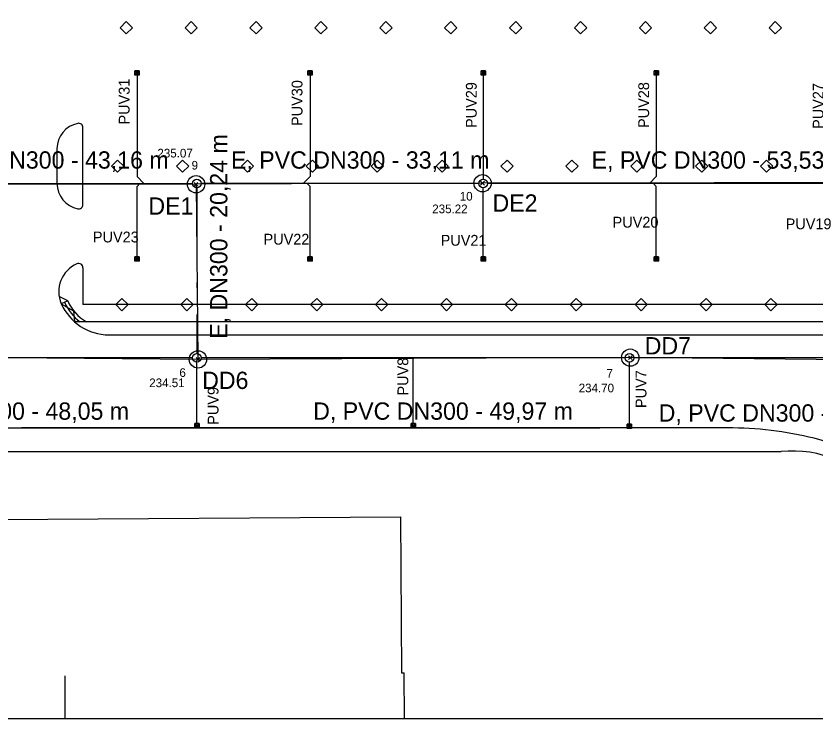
# Model space of a CAD drawing. Extents: x -264234 to -263604, y -1242346 to -1242049.
# Drawn here: x -263924.8 to -263832.4, y -1242345.9 to -1242264.6 of the extents above; entities that cross this region are included whole.
import ezdxf

# ---------------------------------------------------------------- set-up
doc = ezdxf.new("R2010")
doc.units = 0
for name, color, linetype in [('KFA_BODY_CISLO', 7, 'Continuous'), ('KFA_BODY_SYMBOL', 7, 'Continuous'), ('KFA_BODY_VYSKA', 7, 'Continuous'), ('KFA_DAZDOVA_KANALIZACIA_vetva_D', 7, 'Continuous'), ('KFA_DAZDOVA_KANALIZACIA_vetva_D_popis', 7, 'Continuous'), ('KFA_DAZDOVA_KANALIZACIA_vetva_E', 7, 'Continuous'), ('KFA_DAZDOVA_KANALIZACIA_vetva_E_popis', 7, 'Continuous'), ('KFA_SITUACIA_DSP', 7, 'Continuous'), ('KFA_SO_40-2-II_DK_PRIPOJKY_UV_PROJEKT', 7, 'Continuous'), ('KFA_SO_40-2-II_DK_PRIPOJKY_UV_PROJEKT_popis', 7, 'Continuous'), ('KFA_SO_40-2-II_DK_UV_PROJEKT', 7, 'Continuous'), ('RAM_NA_TLAC_1-500', 7, 'Continuous')]:
    doc.layers.add(name, color=color, linetype=linetype)

msp = doc.modelspace()

# ---------------------------------------------------------------- linework, layer by layer
at = {"layer": 'KFA_BODY_SYMBOL'}
for p, q in [((-263871.119, -1242284.177), (-263870.677, -1242283.735)), ((-263870.677, -1242284.177), (-263871.119, -1242283.735)), ((-263904.23, -1242284.301), (-263903.788, -1242283.859)), ((-263903.788, -1242284.301), (-263904.23, -1242283.859)), ((-263904.008, -1242304.539), (-263903.566, -1242304.097)), ((-263903.566, -1242304.539), (-263904.008, -1242304.097)), ((-263854.043, -1242304.34), (-263853.601, -1242303.898)), ((-263853.601, -1242304.34), (-263854.043, -1242303.898))]:
    msp.add_line(p, q, dxfattribs=at)
at = {"layer": 'KFA_DAZDOVA_KANALIZACIA_vetva_D'}
msp.add_lwpolyline([(-263821.591, -1242304.454), (-263853.822, -1242304.119), (-263903.787, -1242304.318), (-263951.83, -1242303.896), (-264004.174, -1242304.048), (-264044.816, -1242304.218), (-264095.209, -1242304.148), (-264105.621, -1242304.173)], dxfattribs=at)
for centre in [(-263853.822, -1242304.119), (-263903.787, -1242304.318)]:
    msp.add_circle(centre, 1, dxfattribs=at)
at = {"layer": 'KFA_DAZDOVA_KANALIZACIA_vetva_E'}
for p, q in [((-263947.171, -1242284.013), (-263904.009, -1242284.08)), ((-263904.009, -1242284.08), (-263903.787, -1242304.318))]:
    msp.add_line(p, q, dxfattribs=at)
msp.add_lwpolyline([(-263817.366, -1242283.882), (-263870.898, -1242283.956), (-263904.009, -1242284.08)], dxfattribs=at)
for centre in [(-263904.009, -1242284.08), (-263870.898, -1242283.956)]:
    msp.add_circle(centre, 1, dxfattribs=at)
at = {"layer": 'KFA_SITUACIA_DSP'}
for p, q in [((-263911.074, -1242270.983), (-263910.574, -1242270.983)), ((-263911.074, -1242271.273), (-263911.074, -1242270.983)), ((-263911.074, -1242270.983), (-263910.574, -1242271.273)), ((-263911.074, -1242270.983), (-263910.574, -1242271.273)), ((-263910.574, -1242270.983), (-263911.074, -1242270.983)), ((-263910.574, -1242271.273), (-263911.074, -1242271.273)), ((-263910.824, -1242271.473), (-263910.824, -1242283.187)), ((-263910.574, -1242270.983), (-263910.574, -1242271.273)), ((-263910.574, -1242271.273), (-263910.574, -1242270.983)), ((-263891.074, -1242270.983), (-263890.574, -1242270.983)), ((-263891.074, -1242271.273), (-263891.074, -1242270.983)), ((-263891.074, -1242270.983), (-263890.574, -1242271.273)), ((-263891.074, -1242270.983), (-263890.574, -1242271.273)), ((-263890.574, -1242270.983), (-263891.074, -1242270.983)), ((-263890.574, -1242271.273), (-263891.074, -1242271.273)), ((-263890.824, -1242271.473), (-263890.824, -1242283.187)), ((-263890.574, -1242270.983), (-263890.574, -1242271.273)), ((-263890.574, -1242271.273), (-263890.574, -1242270.983)), ((-263871.074, -1242270.983), (-263870.574, -1242270.983)), ((-263871.074, -1242271.273), (-263871.074, -1242270.983)), ((-263871.074, -1242270.983), (-263870.574, -1242271.273)), ((-263871.074, -1242270.983), (-263870.574, -1242271.273)), ((-263870.574, -1242270.983), (-263871.074, -1242270.983)), ((-263870.574, -1242271.273), (-263871.074, -1242271.273)), ((-263870.824, -1242271.473), (-263870.824, -1242283.482)), ((-263870.574, -1242270.983), (-263870.574, -1242271.273)), ((-263870.574, -1242271.273), (-263870.574, -1242270.983)), ((-263851.074, -1242270.983), (-263850.574, -1242270.983)), ((-263851.074, -1242271.273), (-263851.074, -1242270.983)), ((-263851.074, -1242270.983), (-263850.574, -1242271.273)), ((-263851.074, -1242270.983), (-263850.574, -1242271.273)), ((-263850.574, -1242270.983), (-263851.074, -1242270.983)), ((-263850.574, -1242271.273), (-263851.074, -1242271.273)), ((-263850.824, -1242271.473), (-263850.824, -1242283.187)), ((-263850.574, -1242270.983), (-263850.574, -1242271.273)), ((-263850.574, -1242271.273), (-263850.574, -1242270.983)), ((-263917.08, -1242286.432), (-263917.08, -1242277.533)), ((-263920.08, -1242279.982), (-263920.08, -1242283.982)), ((-263910.824, -1242283.187), (-263910.029, -1242283.982)), ((-263890.824, -1242283.187), (-263891.619, -1242283.982)), ((-263850.824, -1242283.187), (-263851.619, -1242283.982)), ((-263946.608, -1242283.982), (-263908.955, -1242283.982)), ((-263946.608, -1242283.982), (-263904.413, -1242283.982)), ((-263910.824, -1242284.343), (-263910.499, -1242283.982)), ((-263910.824, -1242292.492), (-263910.824, -1242284.343)), ((-263903.913, -1242284.482), (-263903.913, -1242292.347)), ((-263871.324, -1242283.982), (-263903.413, -1242283.982)), ((-263890.824, -1242284.343), (-263891.149, -1242283.982)), ((-263890.824, -1242292.492), (-263890.824, -1242284.343)), ((-263870.824, -1242292.492), (-263870.824, -1242284.482)), ((-263817.941, -1242283.982), (-263870.324, -1242283.982)), ((-263817.941, -1242283.982), (-263870.324, -1242283.982)), ((-263850.824, -1242284.343), (-263851.149, -1242283.982)), ((-263850.824, -1242292.492), (-263850.824, -1242284.343)), ((-263911.074, -1242292.692), (-263910.574, -1242292.692)), ((-263911.074, -1242292.982), (-263911.074, -1242292.692)), ((-263911.074, -1242292.692), (-263910.574, -1242292.982)), ((-263911.074, -1242292.692), (-263910.574, -1242292.982)), ((-263910.574, -1242292.692), (-263911.074, -1242292.692)), ((-263910.574, -1242292.982), (-263911.074, -1242292.982)), ((-263910.574, -1242292.692), (-263910.574, -1242292.982)), ((-263910.574, -1242292.982), (-263910.574, -1242292.692)), ((-263891.074, -1242292.693), (-263890.574, -1242292.693)), ((-263891.074, -1242292.983), (-263891.074, -1242292.693)), ((-263891.074, -1242292.693), (-263890.574, -1242292.983)), ((-263891.074, -1242292.693), (-263890.574, -1242292.983)), ((-263890.574, -1242292.693), (-263891.074, -1242292.693)), ((-263890.574, -1242292.983), (-263891.074, -1242292.983)), ((-263890.574, -1242292.693), (-263890.574, -1242292.983)), ((-263890.574, -1242292.983), (-263890.574, -1242292.693)), ((-263871.074, -1242292.693), (-263870.574, -1242292.693)), ((-263871.074, -1242292.983), (-263871.074, -1242292.693)), ((-263871.074, -1242292.693), (-263870.574, -1242292.983)), ((-263871.074, -1242292.693), (-263870.574, -1242292.983)), ((-263870.574, -1242292.693), (-263871.074, -1242292.693)), ((-263870.574, -1242292.983), (-263871.074, -1242292.983)), ((-263870.574, -1242292.693), (-263870.574, -1242292.983)), ((-263870.574, -1242292.983), (-263870.574, -1242292.693)), ((-263851.074, -1242292.693), (-263850.574, -1242292.693)), ((-263851.074, -1242292.983), (-263851.074, -1242292.693)), ((-263851.074, -1242292.693), (-263850.574, -1242292.983)), ((-263851.074, -1242292.693), (-263850.574, -1242292.983)), ((-263850.574, -1242292.693), (-263851.074, -1242292.693)), ((-263850.574, -1242292.983), (-263851.074, -1242292.983)), ((-263850.574, -1242292.693), (-263850.574, -1242292.983)), ((-263850.574, -1242292.983), (-263850.574, -1242292.693)), ((-263917.08, -1242293.737), (-263917.08, -1242297.982)), ((-263903.913, -1242295.447), (-263903.913, -1242296.047)), ((-263918.846, -1242297.562), (-263919.828, -1242297.035)), ((-263918.846, -1242297.562), (-263919.579, -1242297.882)), ((-263815.601, -1242297.982), (-263917.08, -1242297.982)), ((-263903.913, -1242299.147), (-263903.913, -1242303.647)), ((-263816.308, -1242299.982), (-263918.049, -1242299.982)), ((-263914.08, -1242301.482), (-263815.822, -1242301.482)), ((-263904.413, -1242304.147), (-263953.413, -1242304.147)), ((-263854.415, -1242304.147), (-263903.413, -1242304.147)), ((-263878.913, -1242311.742), (-263878.913, -1242304.147)), ((-263809.091, -1242304.153), (-263853.415, -1242304.148)), ((-263903.913, -1242311.742), (-263903.913, -1242304.647)), ((-263853.915, -1242311.749), (-263853.915, -1242304.647)), ((-263980.94, -1242312.232), (-263857.327, -1242312.232)), ((-263842.601, -1242312.24), (-263924.192, -1242312.232)), ((-263904.163, -1242311.942), (-263903.663, -1242311.942)), ((-263904.163, -1242312.232), (-263904.163, -1242311.942)), ((-263904.163, -1242311.942), (-263903.663, -1242312.232)), ((-263904.163, -1242311.942), (-263903.663, -1242312.232)), ((-263903.663, -1242311.942), (-263904.163, -1242311.942)), ((-263903.663, -1242312.232), (-263904.163, -1242312.232)), ((-263903.663, -1242311.942), (-263903.663, -1242312.232)), ((-263903.663, -1242312.232), (-263903.663, -1242311.942)), ((-263879.163, -1242311.942), (-263878.663, -1242311.942)), ((-263879.163, -1242312.232), (-263879.163, -1242311.942)), ((-263879.163, -1242311.942), (-263878.663, -1242312.232)), ((-263879.163, -1242311.942), (-263878.663, -1242312.232)), ((-263878.663, -1242311.942), (-263879.163, -1242311.942)), ((-263878.663, -1242312.232), (-263879.163, -1242312.232)), ((-263878.663, -1242311.942), (-263878.663, -1242312.232)), ((-263878.663, -1242312.232), (-263878.663, -1242311.942)), ((-263854.165, -1242311.949), (-263853.665, -1242311.949)), ((-263854.165, -1242312.239), (-263854.165, -1242311.949)), ((-263854.165, -1242311.949), (-263853.665, -1242312.239)), ((-263854.165, -1242311.949), (-263853.665, -1242312.239)), ((-263853.665, -1242311.949), (-263854.165, -1242311.949)), ((-263853.665, -1242312.239), (-263854.165, -1242312.239)), ((-263853.665, -1242311.949), (-263853.665, -1242312.239)), ((-263853.665, -1242312.239), (-263853.665, -1242311.949)), ((-264038.443, -1242314.982), (-263836.403, -1242314.982)), ((-263976.89, -1242323.14), (-263880.39, -1242322.51)), ((-263880.39, -1242322.51), (-263880.27, -1242340.53)), ((-263880.27, -1242340.53), (-263879.95, -1242340.53)), ((-263879.909, -1242345.883), (-263879.95, -1242340.53))]:
    msp.add_line(p, q, dxfattribs=at)
for points in [[(-263912.068, -1242265.279), (-263911.361, -1242265.986), (-263912.068, -1242266.693), (-263912.775, -1242265.986)], [(-263904.568, -1242265.279), (-263903.861, -1242265.986), (-263904.568, -1242266.693), (-263905.275, -1242265.986)], [(-263897.068, -1242265.279), (-263896.361, -1242265.986), (-263897.068, -1242266.693), (-263897.775, -1242265.986)], [(-263897.068, -1242265.279), (-263896.361, -1242265.986), (-263897.068, -1242266.693), (-263897.775, -1242265.986)], [(-263889.568, -1242265.279), (-263888.861, -1242265.986), (-263889.568, -1242266.693), (-263890.275, -1242265.986)], [(-263882.068, -1242265.279), (-263881.361, -1242265.986), (-263882.068, -1242266.693), (-263882.775, -1242265.986)], [(-263874.568, -1242265.279), (-263873.861, -1242265.986), (-263874.568, -1242266.693), (-263875.275, -1242265.986)], [(-263867.068, -1242265.279), (-263866.361, -1242265.986), (-263867.068, -1242266.693), (-263867.775, -1242265.986)], [(-263859.568, -1242265.279), (-263858.861, -1242265.986), (-263859.568, -1242266.693), (-263860.275, -1242265.986)], [(-263852.068, -1242265.279), (-263851.361, -1242265.986), (-263852.068, -1242266.693), (-263852.775, -1242265.986)], [(-263844.568, -1242265.279), (-263843.861, -1242265.986), (-263844.568, -1242266.693), (-263845.275, -1242265.986)], [(-263837.068, -1242265.279), (-263836.361, -1242265.986), (-263837.068, -1242266.693), (-263837.775, -1242265.986)], [(-263913.068, -1242281.275), (-263912.361, -1242281.982), (-263913.068, -1242282.689), (-263913.775, -1242281.982)], [(-263905.568, -1242281.275), (-263904.861, -1242281.982), (-263905.568, -1242282.689), (-263906.275, -1242281.982)], [(-263898.068, -1242281.275), (-263897.361, -1242281.982), (-263898.068, -1242282.689), (-263898.775, -1242281.982)], [(-263890.568, -1242281.275), (-263889.861, -1242281.982), (-263890.568, -1242282.689), (-263891.275, -1242281.982)], [(-263890.568, -1242281.275), (-263889.861, -1242281.982), (-263890.568, -1242282.689), (-263891.275, -1242281.982)], [(-263883.068, -1242281.275), (-263882.361, -1242281.982), (-263883.068, -1242282.689), (-263883.775, -1242281.982)], [(-263875.568, -1242281.275), (-263874.861, -1242281.982), (-263875.568, -1242282.689), (-263876.275, -1242281.982)], [(-263868.068, -1242281.275), (-263867.361, -1242281.982), (-263868.068, -1242282.689), (-263868.775, -1242281.982)], [(-263860.568, -1242281.275), (-263859.861, -1242281.982), (-263860.568, -1242282.689), (-263861.275, -1242281.982)], [(-263853.068, -1242281.275), (-263852.361, -1242281.982), (-263853.068, -1242282.689), (-263853.775, -1242281.982)], [(-263845.568, -1242281.275), (-263844.861, -1242281.982), (-263845.568, -1242282.689), (-263846.275, -1242281.982)], [(-263838.068, -1242281.275), (-263837.361, -1242281.982), (-263838.068, -1242282.689), (-263838.775, -1242281.982)], [(-263912.568, -1242297.275), (-263911.861, -1242297.982), (-263912.568, -1242298.689), (-263913.275, -1242297.982)], [(-263905.068, -1242297.275), (-263904.361, -1242297.982), (-263905.068, -1242298.689), (-263905.775, -1242297.982)], [(-263897.568, -1242297.275), (-263896.861, -1242297.982), (-263897.568, -1242298.689), (-263898.275, -1242297.982)], [(-263890.068, -1242297.275), (-263889.361, -1242297.982), (-263890.068, -1242298.689), (-263890.775, -1242297.982)], [(-263890.068, -1242297.275), (-263889.361, -1242297.982), (-263890.068, -1242298.689), (-263890.775, -1242297.982)], [(-263882.568, -1242297.275), (-263881.861, -1242297.982), (-263882.568, -1242298.689), (-263883.275, -1242297.982)], [(-263875.068, -1242297.275), (-263874.361, -1242297.982), (-263875.068, -1242298.689), (-263875.775, -1242297.982)], [(-263867.568, -1242297.275), (-263866.861, -1242297.982), (-263867.568, -1242298.689), (-263868.275, -1242297.982)], [(-263860.068, -1242297.275), (-263859.361, -1242297.982), (-263860.068, -1242298.689), (-263860.775, -1242297.982)], [(-263852.568, -1242297.275), (-263851.861, -1242297.982), (-263852.568, -1242298.689), (-263853.275, -1242297.982)], [(-263845.068, -1242297.275), (-263844.361, -1242297.982), (-263845.068, -1242298.689), (-263845.775, -1242297.982)], [(-263837.568, -1242297.275), (-263836.861, -1242297.982), (-263837.568, -1242298.689), (-263838.275, -1242297.982)]]:
    msp.add_lwpolyline(points, close=True, dxfattribs=at)
msp.add_lwpolyline([(-263919.579, -1242297.882), (-263918.155, -1242298.713), (-263918.049, -1242299.982)], dxfattribs=at)
for centre, radius in [((-263910.824, -1242271.373), 0.1), ((-263890.824, -1242271.373), 0.1), ((-263870.824, -1242271.373), 0.1), ((-263850.824, -1242271.373), 0.1), ((-263903.913, -1242283.982), 0.5), ((-263870.824, -1242283.982), 0.5), ((-263910.824, -1242292.592), 0.1), ((-263890.824, -1242292.592), 0.1), ((-263870.824, -1242292.592), 0.1), ((-263850.824, -1242292.592), 0.1), ((-263903.913, -1242304.147), 0.5), ((-263853.915, -1242304.147), 0.5), ((-263903.913, -1242311.842), 0.1), ((-263878.913, -1242311.842), 0.1), ((-263853.915, -1242311.849), 0.1)]:
    msp.add_circle(centre, radius, dxfattribs=at)
for centre, radius, start, end in [((-263917.08, -1242279.982), 3, 101.53696, 180), ((-263917.58, -1242277.533), 0.5, 0, 101.53696), ((-263917.08, -1242283.982), 3, 180, 258.46304), ((-263917.58, -1242286.432), 0.5, 258.46304, 0), ((-263916.372, -1242296.482), 3.5, 113.75985, 203.57818), ((-263917.58, -1242293.737), 0.5, 0, 113.75985), ((-263914.08, -1242295.482), 5.2, 203.57818, 239.92665), ((-263914.08, -1242295.482), 6, 203.57818, 270), ((-263914.08, -1242295.482), 5.6, 203.57818, 233.47251), ((-263842.427, -1242353.351), 41.111, 76.13622, 90.24149), ((-263836.184, -1242329.025), 16, 326.2529, 76.96946), ((-263835.045, -1242327.715), 12.805, 36.92053, 96.08735)]:
    msp.add_arc(centre, radius, start, end, dxfattribs=at)
at = {"layer": 'KFA_SO_40-2-II_DK_PRIPOJKY_UV_PROJEKT'}
for points in [[(-263910.824, -1242271.473), (-263910.824, -1242283.187), (-263910.029, -1242283.982)], [(-263890.824, -1242271.473), (-263890.824, -1242283.187), (-263891.619, -1242283.982)], [(-263870.824, -1242271.473), (-263870.824, -1242283.482)], [(-263850.824, -1242271.473), (-263850.824, -1242283.187), (-263851.619, -1242283.982)], [(-263910.824, -1242292.492), (-263910.824, -1242284.343), (-263910.499, -1242283.982)], [(-263890.824, -1242292.492), (-263890.824, -1242284.343), (-263891.149, -1242283.982)], [(-263870.824, -1242292.492), (-263870.824, -1242284.482)], [(-263850.824, -1242292.492), (-263850.824, -1242284.343), (-263851.149, -1242283.982)], [(-263878.913, -1242311.742), (-263878.913, -1242304.147)], [(-263903.913, -1242311.742), (-263903.913, -1242304.647)], [(-263853.915, -1242311.749), (-263853.915, -1242304.647)]]:
    msp.add_lwpolyline(points, dxfattribs=at)
at = {"layer": 'KFA_SO_40-2-II_DK_UV_PROJEKT'}
for points in [[(-263911.074, -1242271.483), (-263911.074, -1242270.983), (-263910.574, -1242270.983), (-263910.574, -1242271.483), (-263911.074, -1242271.483), (-263910.574, -1242270.983), (-263911.074, -1242270.983), (-263910.574, -1242271.483)], [(-263891.074, -1242271.483), (-263891.074, -1242270.983), (-263890.574, -1242270.983), (-263890.574, -1242271.483), (-263891.074, -1242271.483), (-263890.574, -1242270.983), (-263891.074, -1242270.983), (-263890.574, -1242271.483)], [(-263871.074, -1242271.483), (-263871.074, -1242270.983), (-263870.574, -1242270.983), (-263870.574, -1242271.483), (-263871.074, -1242271.483), (-263870.574, -1242270.983), (-263871.074, -1242270.983), (-263870.574, -1242271.483)], [(-263851.074, -1242271.483), (-263851.074, -1242270.983), (-263850.574, -1242270.983), (-263850.574, -1242271.483), (-263851.074, -1242271.483), (-263850.574, -1242270.983), (-263851.074, -1242270.983), (-263850.574, -1242271.483)], [(-263911.074, -1242292.982), (-263911.074, -1242292.482), (-263910.574, -1242292.482), (-263910.574, -1242292.982), (-263911.074, -1242292.982), (-263910.574, -1242292.482), (-263911.074, -1242292.482), (-263910.574, -1242292.982)], [(-263891.074, -1242292.983), (-263891.074, -1242292.483), (-263890.574, -1242292.483), (-263890.574, -1242292.983), (-263891.074, -1242292.983), (-263890.574, -1242292.483), (-263891.074, -1242292.483), (-263890.574, -1242292.983)], [(-263871.074, -1242292.983), (-263871.074, -1242292.483), (-263870.574, -1242292.483), (-263870.574, -1242292.983), (-263871.074, -1242292.983), (-263870.574, -1242292.483), (-263871.074, -1242292.483), (-263870.574, -1242292.983)], [(-263851.074, -1242292.983), (-263851.074, -1242292.483), (-263850.574, -1242292.483), (-263850.574, -1242292.983), (-263851.074, -1242292.983), (-263850.574, -1242292.483), (-263851.074, -1242292.483), (-263850.574, -1242292.983)], [(-263904.163, -1242312.232), (-263904.163, -1242311.732), (-263903.663, -1242311.732), (-263903.663, -1242312.232), (-263904.163, -1242312.232), (-263903.663, -1242311.732), (-263904.163, -1242311.732), (-263903.663, -1242312.232)], [(-263879.163, -1242312.232), (-263879.163, -1242311.732), (-263878.663, -1242311.732), (-263878.663, -1242312.232), (-263879.163, -1242312.232), (-263878.663, -1242311.732), (-263879.163, -1242311.732), (-263878.663, -1242312.232)], [(-263854.165, -1242312.298), (-263854.165, -1242311.798), (-263853.665, -1242311.798), (-263853.665, -1242312.298), (-263854.165, -1242312.298), (-263853.665, -1242311.798), (-263854.165, -1242311.798), (-263853.665, -1242312.298)]]:
    msp.add_lwpolyline(points, dxfattribs=at)
at = {"layer": 'RAM_NA_TLAC_1-500'}
msp.add_line((-263919.177, -1242340.883), (-263919.177, -1242345.883), dxfattribs=at)
msp.add_lwpolyline([(-264234.177, -1242048.883), (-263604.177, -1242048.883), (-263604.177, -1242345.883), (-264234.177, -1242345.883)], close=True, dxfattribs=at)

# ---------------------------------------------------------------- texts
at = {"layer": 'KFA_BODY_CISLO'}
for s, p in [('9', (-263904.525, -1242282.384)), ('10', (-263873.53, -1242285.964)), ('6', (-263905.933, -1242306.346)), ('7', (-263856.576, -1242306.44))]:
    msp.add_text(s, height=1, dxfattribs=at).set_placement(p)
at = {"layer": 'KFA_BODY_VYSKA'}
for s, p in [('235.07', (-263908.474, -1242280.984)), ('235.22', (-263876.712, -1242287.423)), ('234.51', (-263909.421, -1242307.527)), ('234.70', (-263859.788, -1242308.125))]:
    msp.add_text(s, height=1, dxfattribs=at).set_placement(p)
at = {"layer": 'KFA_DAZDOVA_KANALIZACIA_vetva_D_popis'}
for s, p in [('DD7', (-263852.156, -1242303.745)), ('DD6', (-263903.304, -1242307.741)), ('D, PVC DN400 - 48,05 m', (-263941.772, -1242311.294)), ('D, PVC DN300 - 49,97 m', (-263890.474, -1242311.294)), ('D, PVC DN300 - 32,23 m', (-263850.54, -1242311.513))]:
    msp.add_text(s, height=2, dxfattribs=at).set_placement(p)
at = {"layer": 'KFA_DAZDOVA_KANALIZACIA_vetva_E_popis'}
msp.add_text('E, DN300 - 20,24 m', height=2, rotation=90, dxfattribs=at).set_placement((-263900.39, -1242301.934))
for s, p in [('E1, PVC DN300 - 43,16 m', (-263938.542, -1242282.273)), ('E, PVC DN300 - 33,11 m', (-263899.974, -1242282.273)), ('E, PVC DN300 - 53,53 m', (-263858.294, -1242282.275)), ('DE1', (-263909.515, -1242287.598)), ('DE2', (-263869.749, -1242287.248))]:
    msp.add_text(s, height=2, dxfattribs=at).set_placement(p)
at = {"layer": 'KFA_SO_40-2-II_DK_PRIPOJKY_UV_PROJEKT_popis'}
for s, p in [('PUV31', (-263911.688, -1242277.171)), ('PUV30', (-263891.709, -1242277.341)), ('PUV29', (-263871.571, -1242277.572)), ('PUV28', (-263851.647, -1242277.572)), ('PUV27', (-263831.483, -1242277.681)), ('PUV8', (-263879.481, -1242308.499)), ('PUV7', (-263851.953, -1242309.941)), ('PUV9', (-263901.411, -1242311.88))]:
    msp.add_text(s, height=1.25, rotation=90, dxfattribs=at).set_placement(p)
for s, p in [('PUV20', (-263855.864, -1242289.09)), ('PUV19', (-263835.864, -1242289.282)), ('PUV23', (-263915.931, -1242290.801)), ('PUV22', (-263896.208, -1242291.057)), ('PUV21', (-263875.739, -1242291.181))]:
    msp.add_text(s, height=1.25, dxfattribs=at).set_placement(p)

doc.saveas('drawing.dxf')
